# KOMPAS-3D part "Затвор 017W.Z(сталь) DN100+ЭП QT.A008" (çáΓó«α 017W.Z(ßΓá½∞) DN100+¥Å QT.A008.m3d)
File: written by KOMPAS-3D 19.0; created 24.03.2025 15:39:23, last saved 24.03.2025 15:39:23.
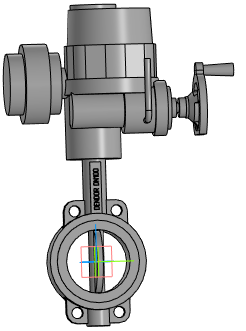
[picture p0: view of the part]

Document properties: Полное имя файла: Затвор 017W.Z(сталь) DN100+ЭП QT.A008.a3d

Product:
- Part/product: Затвор 017W.Z(сталь) DN100+ЭП QT.A008
    Масса: 42.9109

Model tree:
1. Операция без истории:1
